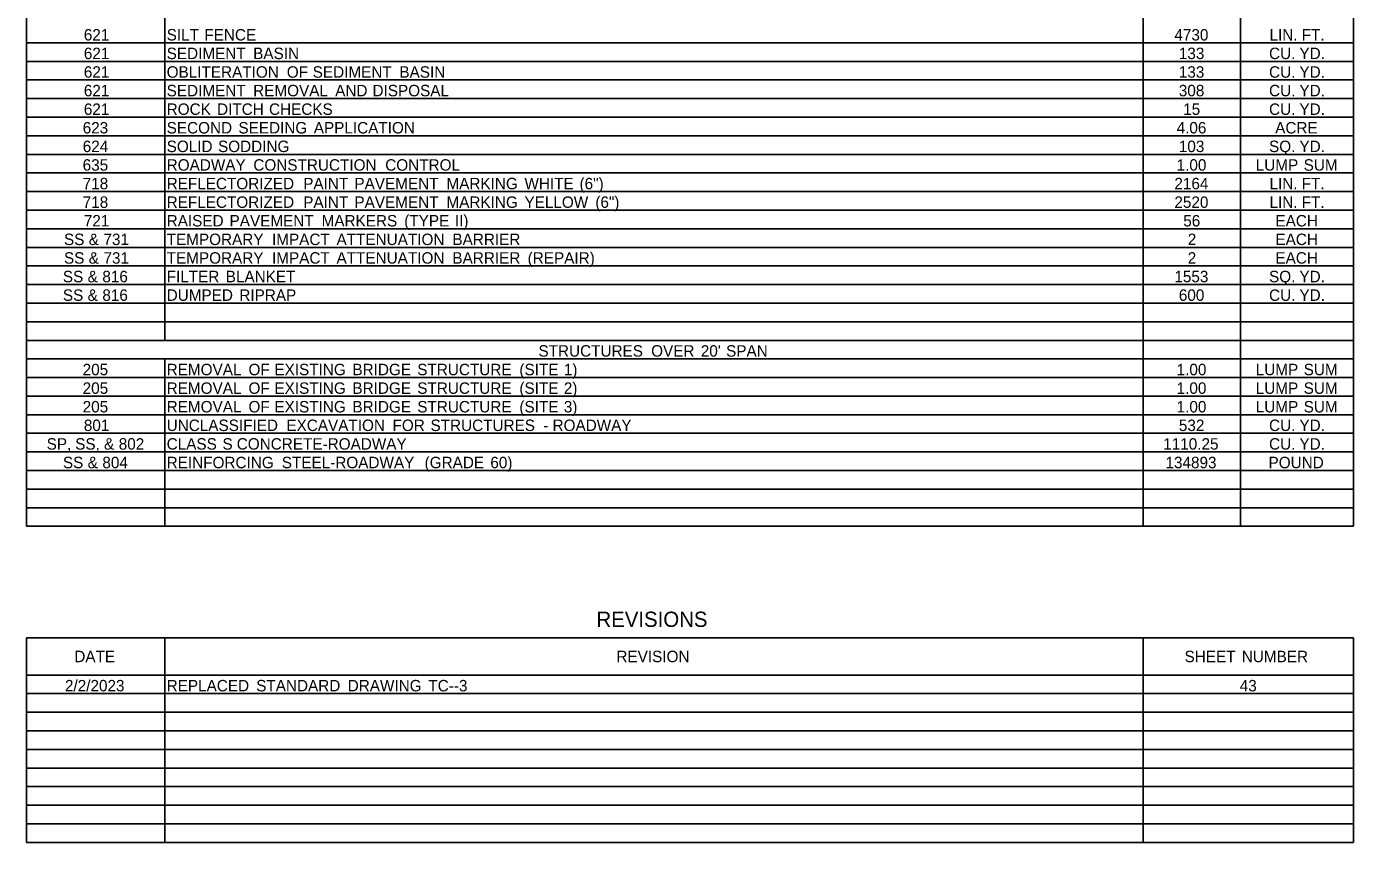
# Model space of a CAD drawing. Extents: x 1955554 to 1962042, y 565952 to 568347.
# Drawn here: x 1960911 to 1961607, y 566047 to 566475 of the extents above; entities that cross this region are included whole.
import ezdxf

# ---------------------------------------------------------------- set-up
doc = ezdxf.new("R2010")
doc.units = 0
doc.layers.add('Default', color=7, linetype='Continuous')

msp = doc.modelspace()

# ---------------------------------------------------------------- linework, layer by layer
at = {"layer": 'Default'}
for p, q in [((1960910.7, 566213.04), (1960910.7, 566885.79)), ((1960910.7, 566213.04), (1960910.7, 566885.79)), ((1960983.24, 566310.54), (1960983.24, 566885.79)), ((1961496.48, 566213.04), (1961496.48, 566885.79)), ((1961547.57, 566213.04), (1961547.57, 566885.79)), ((1961547.57, 566310.54), (1961547.57, 566885.79)), ((1961606.85, 566213.04), (1961606.85, 566885.79)), ((1960983.24, 566310.54), (1960983.24, 566856.54)), ((1961496.48, 566310.54), (1961496.48, 566856.54)), ((1960910.7, 566466.54), (1961606.85, 566466.54)), ((1960910.7, 566456.79), (1961606.85, 566456.79)), ((1960910.7, 566447.04), (1961606.85, 566447.04)), ((1960910.7, 566437.29), (1961606.85, 566437.29)), ((1960910.7, 566427.54), (1961606.85, 566427.54)), ((1960910.7, 566417.79), (1961606.85, 566417.79)), ((1960910.7, 566408.04), (1961606.85, 566408.04)), ((1960910.7, 566398.29), (1961606.85, 566398.29)), ((1960910.7, 566388.54), (1961606.85, 566388.54)), ((1960910.7, 566378.79), (1961606.85, 566378.79)), ((1960910.7, 566369.04), (1961606.85, 566369.04)), ((1960910.7, 566359.29), (1961606.85, 566359.29)), ((1960910.7, 566349.54), (1961606.85, 566349.54)), ((1960910.7, 566339.79), (1961606.85, 566339.79)), ((1960910.7, 566330.04), (1961606.85, 566330.04)), ((1960910.7, 566320.29), (1961606.85, 566320.29)), ((1960910.7, 566310.54), (1961606.85, 566310.54)), ((1961547.57, 566310.54), (1961606.85, 566310.54)), ((1960910.7, 566300.79), (1961606.85, 566300.79)), ((1960983.24, 566213.04), (1960983.24, 566300.79)), ((1960983.24, 566213.04), (1960983.24, 566300.79)), ((1961496.48, 566213.04), (1961496.48, 566300.79)), ((1961547.57, 566213.04), (1961547.57, 566300.79)), ((1960910.7, 566291.04), (1961606.85, 566291.04)), ((1960910.7, 566281.29), (1961606.85, 566281.29)), ((1960910.7, 566271.54), (1961606.85, 566271.54)), ((1960910.7, 566261.79), (1961606.85, 566261.79)), ((1960910.7, 566252.04), (1961606.85, 566252.04)), ((1960910.7, 566242.29), (1961606.85, 566242.29)), ((1960910.7, 566232.54), (1961606.85, 566232.54)), ((1960910.7, 566222.79), (1961606.85, 566222.79)), ((1960910.7, 566213.04), (1961606.85, 566213.04)), ((1960910.7, 566154.54), (1961606.85, 566154.54)), ((1960910.7, 566154.54), (1960983.24, 566154.54)), ((1960910.7, 566047.29), (1960910.7, 566154.54)), ((1960910.7, 566047.29), (1960910.7, 566154.54)), ((1960983.24, 566047.29), (1960983.24, 566154.54)), ((1961496.48, 566154.54), (1961606.85, 566154.54)), ((1961496.48, 566135.04), (1961496.48, 566154.54)), ((1961496.48, 566047.29), (1961496.48, 566154.54)), ((1961606.85, 566047.29), (1961606.85, 566154.54)), ((1960910.7, 566135.04), (1961606.85, 566135.04)), ((1960910.7, 566125.29), (1961606.85, 566125.29)), ((1960910.7, 566115.54), (1961606.85, 566115.54)), ((1960910.7, 566105.79), (1961606.85, 566105.79)), ((1960910.7, 566096.04), (1961606.85, 566096.04)), ((1960910.7, 566086.29), (1961606.85, 566086.29)), ((1960910.7, 566076.54), (1961606.85, 566076.54)), ((1960910.7, 566066.79), (1961606.85, 566066.79)), ((1960910.7, 566057.04), (1961606.85, 566057.04)), ((1960910.7, 566047.29), (1961606.85, 566047.29))]:
    msp.add_line(p, q, dxfattribs=at)

# ---------------------------------------------------------------- texts
for s, height, p in [('621', 6, (1960940.76, 566467.74)), ('SILT', 6, (1960984.22, 566467.74)), (' FENCE', 6, (1961001.75, 566467.74)), ('4730', 6, (1961512.91, 566467.74)), ('LIN.', 6, (1961562.81, 566467.74)), (' FT.', 6, (1961577.45, 566467.74)), ('621', 6, (1960940.76, 566457.99)), ('SEDIMENT', 6, (1960984.22, 566457.99)), (' BASIN', 6, (1961027.37, 566457.99)), ('133', 6, (1961515.23, 566457.99)), ('CU.', 6, (1961562.58, 566457.99)), (' YD.', 6, (1961576.28, 566457.99)), ('621', 6, (1960940.76, 566448.24)), ('OBLITERATION', 6, (1960984.22, 566448.24)), (' OF', 6, (1961045.02, 566448.24)), (' SEDIMENT', 6, (1961058.61, 566448.24)), (' BASIN', 6, (1961104.09, 566448.24)), ('133', 6, (1961515.23, 566448.24)), ('CU.', 6, (1961562.58, 566448.24)), (' YD.', 6, (1961576.28, 566448.24)), ('621', 6, (1960940.76, 566438.49)), ('SEDIMENT', 6, (1960984.22, 566438.49)), (' REMOVAL', 6, (1961027.37, 566438.49)), (' AND', 6, (1961070.4, 566438.49)), (' DISPOSAL', 6, (1961089.98, 566438.49)), ('308', 6, (1961515.22, 566438.49)), ('CU.', 6, (1961562.58, 566438.49)), (' YD.', 6, (1961576.28, 566438.49)), ('621', 6, (1960940.76, 566428.74)), ('ROCK', 6, (1960984.22, 566428.74)), (' DITCH', 6, (1961008.43, 566428.74)), (' CHECKS', 6, (1961035.69, 566428.74)), ('15', 6, (1961517.54, 566428.74)), ('CU.', 6, (1961562.58, 566428.74)), (' YD.', 6, (1961576.28, 566428.74)), ('623', 6, (1960940.17, 566418.99)), ('SECOND', 6, (1960984.22, 566418.99)), (' SEEDING', 6, (1961019.64, 566418.99)), (' APPLICATION', 6, (1961059.18, 566418.99)), ('4.06', 6, (1961514.07, 566418.99)), ('ACRE', 6, (1961565.79, 566418.99)), ('624', 6, (1960940.19, 566409.24)), ('SOLID', 6, (1960984.22, 566409.24)), (' SODDING', 6, (1961008.93, 566409.24)), ('103', 6, (1961515.23, 566409.24)), ('SQ.', 6, (1961562.57, 566409.24)), (' YD.', 6, (1961576.28, 566409.24)), ('635', 6, (1960940.15, 566399.49)), ('ROADWAY', 6, (1960984.22, 566399.49)), (' CONSTRUCTION', 6, (1961027.48, 566399.49)), (' CONTROL', 6, (1961096.66, 566399.49)), ('1.00', 6, (1961514.08, 566399.49)), ('LUMP', 6, (1961555.59, 566399.49)), (' SUM', 6, (1961578.51, 566399.49)), ('718', 6, (1960940.17, 566389.74)), ('REFLECTORIZED', 6, (1960984.22, 566389.74)), (' PAINT', 6, (1961053.65, 566389.74)), (' PAVEMENT', 6, (1961080.49, 566389.74)), (' MARKING', 6, (1961128.78, 566389.74)), (' WHITE', 6, (1961169.71, 566389.74)), (' (6")', 6, (1961198.6, 566389.74)), ('2164', 6, (1961512.91, 566389.74)), ('LIN.', 6, (1961562.81, 566389.74)), (' FT.', 6, (1961577.45, 566389.74)), ('718', 6, (1960940.17, 566379.99)), ('REFLECTORIZED', 6, (1960984.22, 566379.99)), (' PAINT', 6, (1961053.65, 566379.99)), (' PAVEMENT', 6, (1961080.49, 566379.99)), (' MARKING', 6, (1961128.78, 566379.99)), (' YELLOW', 6, (1961169.71, 566379.99)), (' (6")', 6, (1961206.88, 566379.99)), ('2520', 6, (1961512.91, 566379.99)), ('LIN.', 6, (1961562.81, 566379.99)), (' FT.', 6, (1961577.45, 566379.99)), ('721', 6, (1960940.76, 566370.24)), ('RAISED', 6, (1960984.22, 566370.24)), (' PAVEMENT', 6, (1961014.99, 566370.24)), (' MARKERS', 6, (1961063.27, 566370.24)), (' (TYPE', 6, (1961106.63, 566370.24)), (' II)', 6, (1961133.2, 566370.24)), ('56', 6, (1961517.56, 566370.24)), ('EACH', 6, (1961565.91, 566370.24)), ('SS', 6, (1960930.35, 566360.49)), (' &', 6, (1960941.1, 566360.49)), (' 731', 6, (1960948.83, 566360.49)), ('TEMPORARY', 6, (1960984.22, 566360.49)), (' IMPACT', 6, (1961037.26, 566360.49)), (' ATTENUATION', 6, (1961071.1, 566360.49)), (' BARRIER', 6, (1961131.9, 566360.49)), ('2', 6, (1961519.92, 566360.49)), ('EACH', 6, (1961565.91, 566360.49)), ('SS', 6, (1960930.35, 566350.74)), (' &', 6, (1960941.1, 566350.74)), (' 731', 6, (1960948.83, 566350.74)), ('TEMPORARY', 6, (1960984.22, 566350.74)), (' IMPACT', 6, (1961037.26, 566350.74)), (' ATTENUATION', 6, (1961071.1, 566350.74)), (' BARRIER', 6, (1961131.9, 566350.74)), (' (REPAIR)', 6, (1961171.38, 566350.74)), ('2', 6, (1961519.92, 566350.74)), ('EACH', 6, (1961565.91, 566350.74)), ('SS', 6, (1960929.77, 566340.99)), (' &', 6, (1960940.52, 566340.99)), (' 816', 6, (1960948.25, 566340.99)), ('FILTER', 6, (1960984.22, 566340.99)), (' BLANKET', 6, (1961012.99, 566340.99)), ('1553', 6, (1961512.9, 566340.99)), ('SQ.', 6, (1961562.57, 566340.99)), (' YD.', 6, (1961576.28, 566340.99)), ('SS', 6, (1960929.77, 566331.24)), (' &', 6, (1960940.52, 566331.24)), (' 816', 6, (1960948.25, 566331.24)), ('DUMPED', 6, (1960984.22, 566331.24)), (' RIPRAP', 6, (1961020.11, 566331.24)), ('600', 6, (1961515.24, 566331.24)), ('CU.', 6, (1961562.58, 566331.24)), (' YD.', 6, (1961576.28, 566331.24)), ('STRUCTURES', 6, (1961179.28, 566301.99)), (' OVER', 6, (1961236.17, 566301.99)), (" 20'", 6, (1961262.22, 566301.99)), (' SPAN', 6, (1961275.49, 566301.99)), ('205', 6, (1960940.15, 566292.24)), ('REMOVAL', 6, (1960984.22, 566292.24)), (' OF', 6, (1961024.92, 566292.24)), (' EXISTING', 6, (1961038.51, 566292.24)), (' BRIDGE', 6, (1961079.44, 566292.24)), (' STRUCTURE', 6, (1961113.47, 566292.24)), (' (SITE', 6, (1961167.05, 566292.24)), (' 1)', 6, (1961190.36, 566292.24)), ('1.00', 6, (1961514.08, 566292.24)), ('LUMP', 6, (1961555.59, 566292.24)), (' SUM', 6, (1961578.51, 566292.24)), ('205', 6, (1960940.15, 566282.49)), ('REMOVAL', 6, (1960984.22, 566282.49)), (' OF', 6, (1961024.92, 566282.49)), (' EXISTING', 6, (1961038.51, 566282.49)), (' BRIDGE', 6, (1961079.44, 566282.49)), (' STRUCTURE', 6, (1961113.47, 566282.49)), (' (SITE', 6, (1961167.05, 566282.49)), (' 2)', 6, (1961190.36, 566282.49)), ('1.00', 6, (1961514.08, 566282.49)), ('LUMP', 6, (1961555.59, 566282.49)), (' SUM', 6, (1961578.51, 566282.49)), ('205', 6, (1960940.15, 566272.74)), ('REMOVAL', 6, (1960984.22, 566272.74)), (' OF', 6, (1961024.92, 566272.74)), (' EXISTING', 6, (1961038.51, 566272.74)), (' BRIDGE', 6, (1961079.44, 566272.74)), (' STRUCTURE', 6, (1961113.47, 566272.74)), (' (SITE', 6, (1961167.05, 566272.74)), (' 3)', 6, (1961190.36, 566272.74)), ('1.00', 6, (1961514.08, 566272.74)), ('LUMP', 6, (1961555.59, 566272.74)), (' SUM', 6, (1961578.51, 566272.74)), ('801', 6, (1960940.76, 566262.99)), ('UNCLASSIFIED', 6, (1960984.22, 566262.99)), (' EXCAVATION', 6, (1961044.8, 566262.99)), (' FOR', 6, (1961100.49, 566262.99)), (' STRUCTURES', 6, (1961120.4, 566262.99)), (' -', 6, (1961179.59, 566262.99)), (' ROADWAY', 6, (1961184.44, 566262.99)), ('532', 6, (1961515.26, 566262.99)), ('CU.', 6, (1961562.58, 566262.99)), (' YD.', 6, (1961576.28, 566262.99)), ('SP,', 6, (1960921.25, 566253.24)), (' SS,', 6, (1960934.01, 566253.24)), (' &', 6, (1960949.11, 566253.24)), (' 802', 6, (1960956.84, 566253.24)), ('CLASS', 6, (1960984.22, 566253.24)), (' S', 6, (1961011.27, 566253.24)), (' CONCRETE-ROADWAY', 6, (1961018.76, 566253.24)), ('1110.25', 6, (1961507.05, 566253.24)), ('CU.', 6, (1961562.58, 566253.24)), (' YD.', 6, (1961576.28, 566253.24)), ('SS', 6, (1960929.79, 566243.49)), (' &', 6, (1960940.53, 566243.49)), (' 804', 6, (1960948.26, 566243.49)), ('REINFORCING', 6, (1960984.22, 566243.49)), (' STEEL-ROADWAY', 6, (1961042.38, 566243.49)), (' (GRADE', 6, (1961117.32, 566243.49)), (' 60)', 6, (1961151.8, 566243.49)), ('134893', 6, (1961508.24, 566243.49)), ('POUND', 6, (1961562.3, 566243.49)), ('REVISIONS', 8, (1961209.7, 566160.29)), ('DATE', 6, (1960935.77, 566141.79)), ('REVISION', 6, (1961220.17, 566141.79)), ('SHEET', 6, (1961518.24, 566141.79)), (' NUMBER', 6, (1961546.02, 566141.79)), ('2/2/2023', 6, (1960930.86, 566126.49)), ('REPLACED', 6, (1960984.22, 566126.49)), (' STANDARD', 6, (1961028.97, 566126.49)), (' DRAWING', 6, (1961076.97, 566126.49)), (' TC--3', 6, (1961119.29, 566126.49)), ('43', 6, (1961547.2, 566126.49))]:
    msp.add_text(s, height=height, dxfattribs=at).set_placement(p)

doc.saveas('drawing.dxf')
